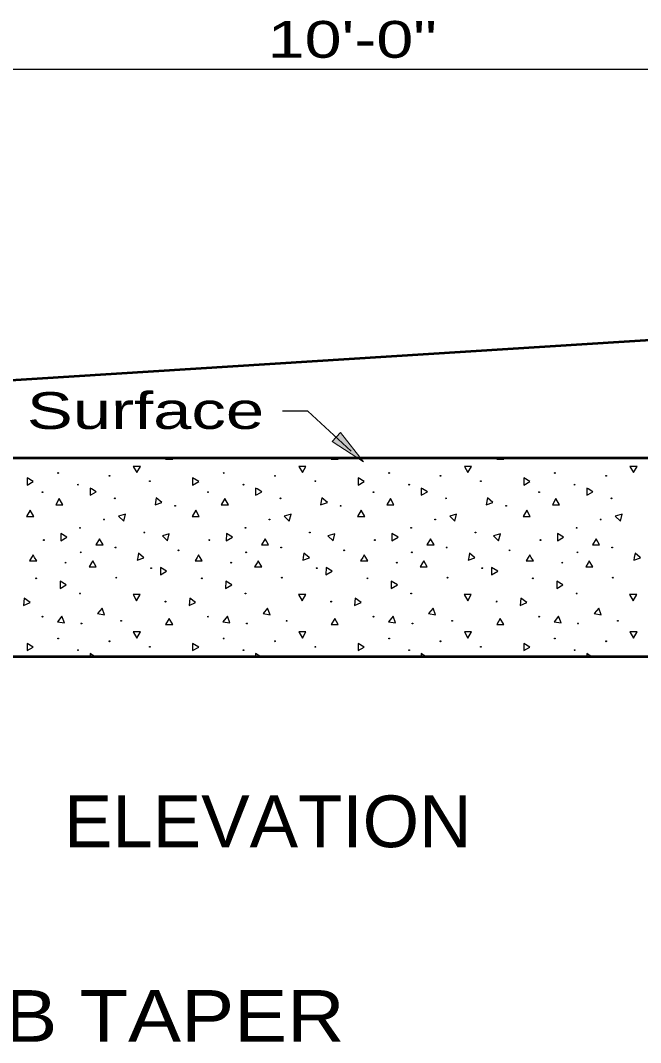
# Model space of a CAD drawing. Extents: x 75.6 to 110.9, y 28 to 50.
# Drawn here: x 85.264 to 87.793, y 35.359 to 39.528 of the extents above; entities that cross this region are included whole.
import ezdxf

# ---------------------------------------------------------------- set-up
doc = ezdxf.new("R2010")
doc.units = 0
doc.header["$LTSCALE"] = 0.06
doc.layers.add('1', color=7, linetype='Continuous', lineweight=25)
doc.layers.add('3', color=7, linetype='Continuous', lineweight=13)

msp = doc.modelspace()

# ---------------------------------------------------------------- hatches: boundary and pattern name
at = {"layer": '3'}
msp.add_hatch(color=256, dxfattribs=at).paths.add_polyline_path([(86.56875, 37.84775), (86.535, 37.81083), (86.66242, 37.72792), (86.66242, 37.72792)])

# ---------------------------------------------------------------- linework, layer by layer
at = {"layer": '1', "lineweight": 53}
for p, q in [((89.3085, 38.31592), (83.31608, 37.94033)), ((83.26617, 37.74358), (90.5905, 37.74358)), ((90.61742, 36.932), (83.26817, 36.932))]:
    msp.add_line(p, q, dxfattribs=at)
at = {"layer": '1'}
for p, q in [((85.85875, 37.74358), (85.85617, 37.73917)), ((86.53375, 37.74358), (86.53117, 37.73917)), ((87.20875, 37.74358), (87.20617, 37.73917)), ((85.54825, 37.6205), (85.54817, 37.59142)), ((85.55408, 37.61717), (85.54825, 37.6205)), ((85.55408, 37.61717), (85.54825, 37.6205)), ((86.22325, 37.6205), (86.22317, 37.59142)), ((86.22908, 37.61717), (86.22325, 37.6205)), ((86.22908, 37.61717), (86.22325, 37.6205)), ((86.89825, 37.6205), (86.89817, 37.59142)), ((86.90408, 37.61717), (86.89825, 37.6205)), ((86.90408, 37.61717), (86.89825, 37.6205)), ((87.57325, 37.6205), (87.57317, 37.59142)), ((87.57908, 37.61717), (87.57325, 37.6205)), ((87.57908, 37.61717), (87.57325, 37.6205)), ((85.54817, 37.59142), (85.55408, 37.59475)), ((86.22317, 37.59142), (86.22908, 37.59475)), ((86.89817, 37.59142), (86.90408, 37.59475)), ((87.57317, 37.59142), (87.57908, 37.59475)), ((85.30975, 37.338), (85.30125, 37.32358)), ((85.30125, 37.32358), (85.3305, 37.32358)), ((85.3305, 37.32358), (85.32208, 37.338)), ((85.55408, 37.316), (85.54417, 37.29892)), ((85.55875, 37.32408), (85.55408, 37.316)), ((85.57325, 37.29892), (85.55875, 37.32408)), ((85.74225, 37.338), (85.74025, 37.32658)), ((85.74025, 37.32658), (85.7675, 37.33667)), ((85.7675, 37.33667), (85.76583, 37.338)), ((85.98475, 37.338), (85.97625, 37.32358)), ((85.97625, 37.32358), (86.0055, 37.32358)), ((86.0055, 37.32358), (85.99708, 37.338)), ((86.22908, 37.316), (86.21917, 37.29892)), ((86.23375, 37.32408), (86.22908, 37.316)), ((86.24825, 37.29892), (86.23375, 37.32408)), ((86.41725, 37.338), (86.41525, 37.32658)), ((86.41525, 37.32658), (86.4425, 37.33667)), ((86.4425, 37.33667), (86.44083, 37.338)), ((86.65975, 37.338), (86.65125, 37.32358)), ((86.65125, 37.32358), (86.6805, 37.32358)), ((86.6805, 37.32358), (86.67208, 37.338)), ((86.90408, 37.316), (86.89417, 37.29892)), ((86.90875, 37.32408), (86.90408, 37.316)), ((86.92325, 37.29892), (86.90875, 37.32408)), ((87.09225, 37.338), (87.09025, 37.32658)), ((87.09025, 37.32658), (87.1175, 37.33667)), ((87.1175, 37.33667), (87.11583, 37.338)), ((87.33475, 37.338), (87.32625, 37.32358)), ((87.32625, 37.32358), (87.3555, 37.32358)), ((87.3555, 37.32358), (87.34708, 37.338)), ((87.57908, 37.316), (87.56917, 37.29892)), ((87.58375, 37.32408), (87.57908, 37.316)), ((87.59825, 37.29892), (87.58375, 37.32408)), ((87.76725, 37.338), (87.76525, 37.32658)), ((87.76525, 37.32658), (87.7925, 37.33667)), ((87.7925, 37.33667), (87.79083, 37.338)), ((85.54417, 37.29892), (85.55408, 37.29892)), ((85.55408, 37.29892), (85.57325, 37.29892)), ((86.21917, 37.29892), (86.22908, 37.29892)), ((86.22908, 37.29892), (86.24825, 37.29892)), ((86.89417, 37.29892), (86.90408, 37.29892)), ((86.90408, 37.29892), (86.92325, 37.29892)), ((87.56917, 37.29892), (87.57908, 37.29892)), ((87.57908, 37.29892), (87.59825, 37.29892)), ((85.54825, 36.9455), (85.54825, 36.932)), ((85.54825, 36.9455), (85.54825, 36.932)), ((85.55408, 36.94217), (85.54825, 36.9455)), ((85.55408, 36.94217), (85.54825, 36.9455)), ((85.57158, 36.932), (85.55408, 36.94217)), ((86.22325, 36.9455), (86.22325, 36.932)), ((86.22325, 36.9455), (86.22325, 36.932)), ((86.22908, 36.94217), (86.22325, 36.9455)), ((86.22908, 36.94217), (86.22325, 36.9455)), ((86.24658, 36.932), (86.22908, 36.94217)), ((86.89825, 36.9455), (86.89825, 36.932)), ((86.89825, 36.9455), (86.89825, 36.932)), ((86.90408, 36.94217), (86.89825, 36.9455)), ((86.90408, 36.94217), (86.89825, 36.9455)), ((86.92158, 36.932), (86.90408, 36.94217)), ((87.57325, 36.9455), (87.57325, 36.932)), ((87.57325, 36.9455), (87.57325, 36.932)), ((87.57908, 36.94217), (87.57325, 36.9455)), ((87.57908, 36.94217), (87.57325, 36.9455)), ((87.59658, 36.932), (87.57908, 36.94217))]:
    msp.add_line(p, q, dxfattribs=at)
for points in [[(85.85617, 37.73917), (85.88525, 37.73917), (85.88267, 37.74358)], [(86.53117, 37.73917), (86.56025, 37.73917), (86.55767, 37.74358)], [(87.20617, 37.73917), (87.23525, 37.73917), (87.23267, 37.74358)], [(85.54825, 37.6205), (85.54817, 37.59142), (85.55408, 37.59475)], [(85.55408, 37.59475), (85.57342, 37.60592), (85.55408, 37.61717)], [(86.22325, 37.6205), (86.22317, 37.59142), (86.22908, 37.59475)], [(86.22908, 37.59475), (86.24842, 37.60592), (86.22908, 37.61717)], [(86.89825, 37.6205), (86.89817, 37.59142), (86.90408, 37.59475)], [(86.90408, 37.59475), (86.92342, 37.60592), (86.90408, 37.61717)], [(87.57325, 37.6205), (87.57317, 37.59142), (87.57908, 37.59475)], [(87.57908, 37.59475), (87.59842, 37.60592), (87.57908, 37.61717)], [(85.76583, 37.338), (85.74533, 37.35517), (85.74225, 37.338)], [(85.76583, 37.338), (85.74533, 37.35517), (85.74225, 37.338)], [(86.44083, 37.338), (86.42033, 37.35517), (86.41725, 37.338)], [(86.44083, 37.338), (86.42033, 37.35517), (86.41725, 37.338)], [(87.11583, 37.338), (87.09533, 37.35517), (87.09225, 37.338)], [(87.11583, 37.338), (87.09533, 37.35517), (87.09225, 37.338)], [(87.79083, 37.338), (87.77033, 37.35517), (87.76725, 37.338)], [(87.79083, 37.338), (87.77033, 37.35517), (87.76725, 37.338)], [(85.32208, 37.338), (85.31592, 37.34867), (85.30975, 37.338)], [(85.99708, 37.338), (85.99092, 37.34867), (85.98475, 37.338)], [(86.67208, 37.338), (86.66592, 37.34867), (86.65975, 37.338)], [(87.34708, 37.338), (87.34092, 37.34867), (87.33475, 37.338)]]:
    msp.add_lwpolyline(points, dxfattribs=at)
for points in [[(85.73883, 37.68408), (85.7535, 37.70933), (85.72433, 37.70933)], [(86.41383, 37.68408), (86.4285, 37.70933), (86.39933, 37.70933)], [(87.08883, 37.68408), (87.1035, 37.70933), (87.07433, 37.70933)], [(87.76383, 37.68408), (87.7785, 37.70933), (87.74933, 37.70933)], [(85.29108, 37.63275), (85.31633, 37.64733), (85.29125, 37.66192)], [(85.96608, 37.63275), (85.99133, 37.64733), (85.96625, 37.66192)], [(86.64108, 37.63275), (86.66633, 37.64733), (86.64125, 37.66192)], [(87.31608, 37.63275), (87.34133, 37.64733), (87.31625, 37.66192)], [(85.408, 37.55258), (85.43708, 37.55258), (85.42258, 37.57767)], [(85.81325, 37.55192), (85.84058, 37.56192), (85.81833, 37.5805)], [(86.083, 37.55258), (86.11208, 37.55258), (86.09758, 37.57767)], [(86.48825, 37.55192), (86.51558, 37.56192), (86.49333, 37.5805)], [(86.758, 37.55258), (86.78708, 37.55258), (86.77258, 37.57767)], [(87.16325, 37.55192), (87.19058, 37.56192), (87.16833, 37.5805)], [(87.433, 37.55258), (87.46208, 37.55258), (87.44758, 37.57767)], [(85.28917, 37.50533), (85.31825, 37.50533), (85.30375, 37.5305)], [(85.96417, 37.50533), (85.99325, 37.50533), (85.97875, 37.5305)], [(86.63917, 37.50533), (86.66825, 37.50533), (86.65375, 37.5305)], [(87.31417, 37.50533), (87.34325, 37.50533), (87.32875, 37.5305)], [(85.68525, 37.48592), (85.69275, 37.51417), (85.66475, 37.50658)], [(86.36025, 37.48592), (86.36775, 37.51417), (86.33975, 37.50658)], [(87.03525, 37.48592), (87.04275, 37.51417), (87.01475, 37.50658)], [(87.71025, 37.48592), (87.71775, 37.51417), (87.68975, 37.50658)], [(85.42867, 37.40592), (85.45392, 37.4205), (85.42883, 37.43508)], [(85.57175, 37.38892), (85.60092, 37.38892), (85.58642, 37.41417)], [(85.86367, 37.40592), (85.87117, 37.43408), (85.84308, 37.42658)], [(86.10367, 37.40592), (86.12892, 37.4205), (86.10383, 37.43508)], [(86.24675, 37.38892), (86.27592, 37.38892), (86.26142, 37.41417)], [(86.53867, 37.40592), (86.54617, 37.43408), (86.51808, 37.42658)], [(86.77867, 37.40592), (86.80392, 37.4205), (86.77883, 37.43508)], [(86.92175, 37.38892), (86.95092, 37.38892), (86.93642, 37.41417)], [(87.21367, 37.40592), (87.22117, 37.43408), (87.19308, 37.42658)], [(87.45367, 37.40592), (87.47892, 37.4205), (87.45383, 37.43508)], [(87.59675, 37.38892), (87.62592, 37.38892), (87.61142, 37.41417)], [(85.835, 37.2675), (85.86025, 37.28208), (85.83517, 37.29667)], [(86.51, 37.2675), (86.53525, 37.28208), (86.51017, 37.29667)], [(87.185, 37.2675), (87.21025, 37.28208), (87.18517, 37.29667)], [(85.426, 37.21175), (85.45125, 37.22642), (85.42617, 37.24092)], [(86.101, 37.21175), (86.12625, 37.22642), (86.10117, 37.24092)], [(86.776, 37.21175), (86.80125, 37.22642), (86.77617, 37.24092)], [(87.451, 37.21175), (87.47625, 37.22642), (87.45117, 37.24092)], [(85.73775, 37.16117), (85.75233, 37.18642), (85.72325, 37.18642)], [(86.41275, 37.16117), (86.42733, 37.18642), (86.39825, 37.18642)], [(87.08775, 37.16117), (87.10233, 37.18642), (87.07325, 37.18642)], [(87.76275, 37.16117), (87.77733, 37.18642), (87.74825, 37.18642)], [(85.27692, 37.14233), (85.30333, 37.15458), (85.2795, 37.17125)], [(85.95192, 37.14233), (85.97833, 37.15458), (85.9545, 37.17125)], [(86.62692, 37.14233), (86.65333, 37.15458), (86.6295, 37.17125)], [(87.30192, 37.14233), (87.32833, 37.15458), (87.3045, 37.17125)], [(85.57833, 37.10925), (85.607, 37.10417), (85.59708, 37.1315)], [(86.25333, 37.10925), (86.282, 37.10417), (86.27208, 37.1315)], [(86.92833, 37.10925), (86.957, 37.10417), (86.94708, 37.1315)], [(87.60333, 37.10925), (87.632, 37.10417), (87.62208, 37.1315)], [(85.41483, 37.07575), (85.4435, 37.07067), (85.4335, 37.09808)], [(85.85617, 37.06417), (85.88525, 37.06417), (85.87075, 37.08925)], [(86.08983, 37.07575), (86.1185, 37.07067), (86.1085, 37.09808)], [(86.53117, 37.06417), (86.56025, 37.06417), (86.54575, 37.08925)], [(86.76483, 37.07575), (86.7935, 37.07067), (86.7835, 37.09808)], [(87.20617, 37.06417), (87.23525, 37.06417), (87.22075, 37.08925)], [(87.43983, 37.07575), (87.4685, 37.07067), (87.4585, 37.09808)], [(85.73883, 37.00908), (85.7535, 37.03433), (85.72433, 37.03433)], [(86.41383, 37.00908), (86.4285, 37.03433), (86.39933, 37.03433)], [(87.08883, 37.00908), (87.1035, 37.03433), (87.07433, 37.03433)], [(87.76383, 37.00908), (87.7785, 37.03433), (87.74933, 37.03433)], [(85.29108, 36.95775), (85.31633, 36.97233), (85.29125, 36.98692)], [(85.96608, 36.95775), (85.99133, 36.97233), (85.96625, 36.98692)], [(86.64108, 36.95775), (86.66633, 36.97233), (86.64125, 36.98692)], [(87.31608, 36.95775), (87.34133, 36.97233), (87.31625, 36.98692)]]:
    msp.add_lwpolyline(points, close=True, dxfattribs=at)
for centre in [(85.41796, 37.68203), (85.62721, 37.67089), (85.79174, 37.64856), (86.09296, 37.68203), (86.30221, 37.67089), (86.46674, 37.64856), (86.76796, 37.68203), (86.97721, 37.67089), (87.14174, 37.64856), (87.44296, 37.68203), (87.65221, 37.67089), (85.35383, 37.60395), (85.49885, 37.63461), (86.02883, 37.60395), (86.17385, 37.63461), (86.70383, 37.60395), (86.84885, 37.63461), (87.37883, 37.60395), (87.52385, 37.63461), (85.64948, 37.57886), (86.32448, 37.57886), (86.99948, 37.57886), (87.67448, 37.57886), (85.89496, 37.54815), (86.56996, 37.54815), (87.24496, 37.54815), (85.60488, 37.49241), (86.27988, 37.49241), (86.95488, 37.49241), (87.62988, 37.49241), (85.50723, 37.45894), (85.76941, 37.43936), (86.18223, 37.45894), (86.44441, 37.43936), (86.85723, 37.45894), (87.11941, 37.43936), (87.53223, 37.45894), (85.3594, 37.40871), (86.0344, 37.40871), (86.7094, 37.40871), (87.3844, 37.40871), (85.50998, 37.35853), (85.6523, 37.37805), (85.90891, 37.36686), (86.18498, 37.35853), (86.3273, 37.37805), (86.58391, 37.36686), (86.85998, 37.35853), (87.0023, 37.37805), (87.25891, 37.36686), (87.53498, 37.35853), (87.6773, 37.37805), (85.44861, 37.31663), (86.12361, 37.31663), (86.79861, 37.31663), (87.47361, 37.31663), (85.79731, 37.29429), (86.47231, 37.29429), (87.14731, 37.29429), (85.32869, 37.2525), (85.65505, 37.25526), (86.00369, 37.2525), (86.33005, 37.25526), (86.67869, 37.2525), (87.00505, 37.25526), (87.35369, 37.2525), (87.68005, 37.25526), (85.50723, 37.19113), (86.18223, 37.19113), (86.85723, 37.19113), (87.53223, 37.19113), (85.85586, 37.15766), (86.53086, 37.15766), (87.20586, 37.15766), (85.35383, 37.09629), (85.5128, 37.06839), (85.67463, 37.07953), (86.02883, 37.09629), (86.1878, 37.06839), (86.34963, 37.07953), (86.70383, 37.09629), (86.8628, 37.06839), (87.02463, 37.07953), (87.37883, 37.09629), (87.5378, 37.06839), (87.69963, 37.07953), (85.41796, 37.00703), (85.62721, 36.99589), (86.09296, 37.00703), (86.30221, 36.99589), (86.76796, 37.00703), (86.97721, 36.99589), (87.44296, 37.00703), (87.65221, 36.99589), (85.49885, 36.95961), (85.79174, 36.97356), (86.17385, 36.95961), (86.46674, 36.97356), (86.84885, 36.95961), (87.14174, 36.97356), (87.52385, 36.95961)]:
    msp.add_circle(centre, 0.00162, dxfattribs=at)
for centre in [(85.5128, 37.74339), (86.1878, 37.74339), (86.8628, 37.74339), (87.5378, 37.74339)]:
    msp.add_arc(centre, 0.00162, 173.26839, 6.73161, dxfattribs=at)
at = {"layer": '3', "lineweight": 25}
msp.add_line((83.42208, 39.32883), (89.60558, 39.32883), dxfattribs=at)
msp.add_lwpolyline([(86.61317, 37.7715), (86.43617, 37.93442), (86.33317, 37.93442)], dxfattribs=at)
at = {"layer": '3'}
msp.add_lwpolyline([(86.56875, 37.84775), (86.535, 37.81083), (86.66242, 37.72792), (86.66242, 37.72792)], close=True, dxfattribs=at)

# ---------------------------------------------------------------- texts
for s, height, width, p in [('10\'-0"', 0.15, 1.35, (86.27242, 39.37575)), ('Surface', 0.15, 1.4, (85.29033, 37.86183)), ('ELEVATION', 0.2109, 1.05, (85.44158, 36.15608)), ('STANDARD CURB TAPER', 0.2109, 1.15, (82.62167, 35.36225))]:
    msp.add_text(s, height=height, dxfattribs=dict(at, width=width)).set_placement(p)

doc.saveas('drawing.dxf')
